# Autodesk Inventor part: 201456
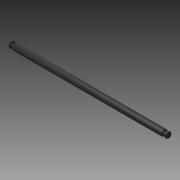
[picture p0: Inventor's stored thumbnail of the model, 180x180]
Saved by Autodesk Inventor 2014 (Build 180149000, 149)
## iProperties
Created: 2007-10
Part Number: 201456
Document SubType Name: Modeling
Designer: TT
Density: 7.85 g/cm^3
Mass: 599.106 g
Surface Area: 203.247 cm^2
Volume: 76.3193 cm^3
Material: Steel
Description: HOR SUPPORT BAR
Appearance: Rubber - Black - Version 1.1
Component Category: Lower Component
Author: TT
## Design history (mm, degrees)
sketch "Sketch1"
  geometry: L1 (200.198, 0)-(-200.198, 0); L2 (-200.198, 0)-(-200.198, 5.045); L3 (-197.323, 7.92)-(-197.248, 7.92); L4 (-197.248, 7.92)-(-197.248, 4.18); L5 (-197.248, 4.18)-(-188.748, 4.18); L6 (-188.748, 4.18)-(-188.748, 7.92); L7 (-188.748, 7.92)-(188.748, 7.92); L8 (188.748, 7.92)-(188.748, 4.18); L9 (188.748, 4.18)-(197.248, 4.18); L10 (197.248, 4.18)-(197.248, 7.92); L11 (197.248, 7.92)-(197.323, 7.92); L12 (200.198, 5.045)-(200.198, 0); A1 r 2.875 centre (-197.323, 5.045) between (-197.323, 7.92) and (-200.198, 5.045); A2 r 2.875 centre (197.323, 5.045) between (200.198, 5.045) and (197.323, 7.92); 2 further points
  constraints: 24 end point, 7 parallel, 4 point on circle, 4 tangent, 2 centre point, 2 collinear, 2 perpendicular, 1 coincident, 1 equal radius, 1 horizontal, 1 midpoint
  dimensions: "d0" = 400.396 distance of L1.start L1.end; "d2" = 15.84 diameter of L7 L1; "d4" = 8.36 diameter of L5 L1; "d5" = 15.84 diameter of L3 L1; "d7" = 8.36 diameter of L9 L1 (= d4); "d8" = 15.84 diameter of L11 L1 (= d5); "d15" = 2.875 radius of A1; "d21" = 2.95 distance between parallel lines of L4 L2; "d22" = 8.5 distance of L4.end L5.end; "d23" = 2.95 distance between parallel lines of L10 L12; "d24" = 8.5 distance of L8.end L9.end (= d22)
revolve "Revolution1" sketch "Sketch1" stored, may be unused: angle "d16" = 90 deg
chamfer "Chamfer1" distance "d17" = 0.375; stored, may be unused: second distance "d18" = 2, angle "d19" = 45 deg
fillet "Fillet1" dims "d20" = 0.5
body "Solid1"
